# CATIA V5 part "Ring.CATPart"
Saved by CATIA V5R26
Part number: Part1.1
Bounding box of the stored display mesh (mm): x -5 to 5, y -15 to 15, z -15 to 15
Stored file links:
  D:\_Deepak\CATIA\CATIA V5-6R2016_Deepak\Resources\Part files\Partfiles\c12_catia_v5_6r2016_prt\c12_catia_v5-6r2016 figr_12-12\Ring.CATPart
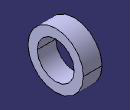
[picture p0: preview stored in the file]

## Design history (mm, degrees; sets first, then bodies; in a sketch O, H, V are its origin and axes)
Body1 (main body)
  Sketch1 on yz-plane, origin (0, 0, 0), H (0, 1, 0), V (0, 0, 1)
    circle A1 centre (0, 0) radius 15
    circle A2 centre (0, 0) radius 10
    radius A1 = 15
    radius A2 = 10
  Pad1: profile Sketch1, direction (1, 0, 0), length 5, mirrored extent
